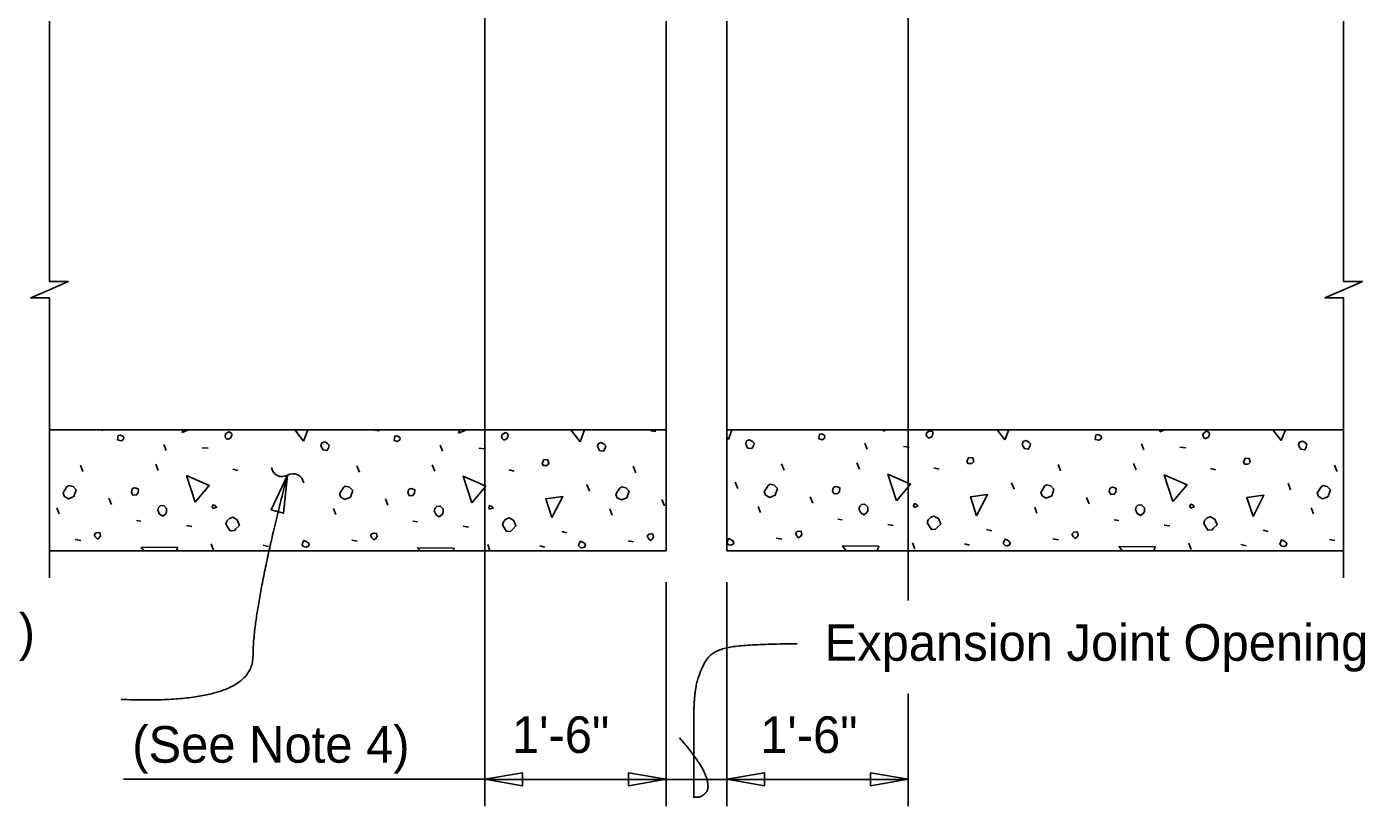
# Model space of a CAD drawing. Extents: x 110698 to 110915, y 110390 to 110472.
# Drawn here: x 110797.65 to 110805.03, y 110451.49 to 110455.78 of the extents above; entities that cross this region are included whole.
import ezdxf

# ---------------------------------------------------------------- set-up
doc = ezdxf.new("R2010")
doc.units = 0
for name, color, linetype in [('AdhocPoint_dp', 7, 'Continuous'), ('Border', 7, 'Continuous'), ('PlotBorder_dp', 7, 'Continuous'), ('SheetBorder_dp', 7, 'Continuous'), ('SheetLines_dp', 7, 'Continuous')]:
    doc.layers.add(name, color=color, linetype=linetype)

msp = doc.modelspace()

# ---------------------------------------------------------------- linework, layer by layer
at = {"layer": 'AdhocPoint_dp'}
for p, q in [((110800.1776, 110464.1815), (110800.1776, 110451.4891)), ((110802.5109, 110464.1815), (110802.5109, 110452.6217)), ((110802.5109, 110452.1086), (110802.5109, 110451.4891))]:
    msp.add_line(p, q, dxfattribs=at)
at = {"layer": 'Border'}
msp.add_line((110800.1776, 110451.6372), (110798.185, 110451.6372), dxfattribs=at)
at = {"layer": 'PlotBorder_dp'}
for p, q in [((110801.1776, 110452.7232), (110801.1776, 110451.4891)), ((110801.5109, 110452.7232), (110801.5109, 110451.4891)), ((110802.5109, 110451.6371), (110800.1776, 110451.6371))]:
    msp.add_line(p, q, dxfattribs=at)
for points in [[(110797.7777, 110455.8133), (110797.7777, 110454.3793), (110797.8811, 110454.3793), (110797.7777, 110454.3343), (110797.6744, 110454.2893), (110797.7777, 110454.2893), (110797.7777, 110452.7468)], [(110804.9108, 110455.8133), (110804.9108, 110454.3793), (110805.0141, 110454.3793), (110804.9108, 110454.3343), (110804.8075, 110454.2893), (110804.9108, 110454.2893), (110804.9108, 110452.7468)]]:
    msp.add_lwpolyline(points, dxfattribs=at)
for points in [[(110799.0893, 110453.3129), (110799.067, 110453.1028), (110798.9991, 110453.1219)], [(110800.1776, 110451.6372), (110800.3858, 110451.6725), (110800.3858, 110451.602)], [(110801.1776, 110451.6372), (110800.9693, 110451.602), (110800.9693, 110451.6725)], [(110801.5109, 110451.6372), (110801.7192, 110451.602), (110801.7192, 110451.6725)], [(110802.5109, 110451.6372), (110802.3027, 110451.6725), (110802.3027, 110451.602)]]:
    msp.add_lwpolyline(points, close=True, dxfattribs=at)
for centre, start, end in [((110799.0602, 110453.364), 188.42943, 300.15665), ((110799.1201, 110453.2609), 8.42943, 120.15665)]:
    msp.add_arc(centre, 0.0596, start, end, dxfattribs=at)
for points in [[(110798.1728, 110452.0773), (110798.8987, 110452.0476), (110798.9003, 110452.5839), (110799.0894, 110453.3127)], [(110801.2506, 110451.8656), (110801.3686, 110451.7293), (110801.4201, 110451.59), (110801.3717, 110451.5386), (110801.3286, 110451.5386), (110801.3286, 110451.5386), (110801.3286, 110451.7899), (110801.3286, 110452.0927), (110801.3596, 110452.229), (110801.4322, 110452.3532), (110801.6653, 110452.3834), (110801.8984, 110452.3834)]]:
    msp.add_open_spline(points, degree=2, dxfattribs=at)
at = {"layer": 'SheetBorder_dp'}
for p, q in [((110798.0532, 110453.5632), (110798.072, 110453.5595)), ((110799.5693, 110453.5613), (110799.5958, 110453.556)), ((110801.0931, 110453.5577), (110801.1196, 110453.5524)), ((110803.4597, 110453.5632), (110803.4608, 110453.563)), ((110798.4202, 110453.4481), (110798.4079, 110453.4817)), ((110798.62, 110453.464), (110798.6518, 110453.4605)), ((110799.9441, 110453.4446), (110799.9317, 110453.4782)), ((110802.2852, 110453.4552), (110802.2728, 110453.4888)), ((110802.4849, 110453.4711), (110802.5168, 110453.4676)), ((110803.809, 110453.4517), (110803.7966, 110453.4852)), ((110804.0088, 110453.4676), (110804.0406, 110453.464)), ((110800.1438, 110453.4605), (110800.1756, 110453.457)), ((110797.9624, 110453.3332), (110797.9482, 110453.3686)), ((110798.3778, 110453.3385), (110798.3637, 110453.3739)), ((110798.7879, 110453.3456), (110798.8162, 110453.3385)), ((110799.4862, 110453.3297), (110799.4721, 110453.365)), ((110799.9016, 110453.335), (110799.8875, 110453.3703)), ((110800.3117, 110453.3421), (110800.34, 110453.335)), ((110801.01, 110453.3261), (110800.9959, 110453.3615)), ((110801.8273, 110453.3403), (110801.8132, 110453.3756)), ((110802.2428, 110453.3456), (110802.2286, 110453.3809)), ((110802.6529, 110453.3527), (110802.6812, 110453.3456)), ((110803.3512, 110453.3368), (110803.337, 110453.3721)), ((110803.7666, 110453.3421), (110803.7524, 110453.3774)), ((110804.1767, 110453.3491), (110804.205, 110453.3421)), ((110804.875, 110453.3332), (110804.8608, 110453.3686)), ((110800.7537, 110453.2254), (110800.7395, 110453.2607)), ((110801.571, 110453.2395), (110801.5569, 110453.2749)), ((110803.0948, 110453.236), (110803.0807, 110453.2713)), ((110804.6186, 110453.2325), (110804.6045, 110453.2678)), ((110798.1197, 110453.1511), (110798.1056, 110453.1865)), ((110799.6435, 110453.1476), (110799.6294, 110453.183)), ((110801.1673, 110453.1441), (110801.1532, 110453.1794)), ((110801.9847, 110453.1582), (110801.9705, 110453.1936)), ((110803.5085, 110453.1547), (110803.4943, 110453.19)), ((110797.8316, 110453.0999), (110797.8192, 110453.1335)), ((110799.3554, 110453.0963), (110799.343, 110453.1299)), ((110800.8792, 110453.0928), (110800.8668, 110453.1264)), ((110801.6965, 110453.1069), (110801.6841, 110453.1405)), ((110803.2203, 110453.1034), (110803.208, 110453.137)), ((110804.7442, 110453.0999), (110804.7318, 110453.1335)), ((110798.2576, 110453.0627), (110798.2823, 110453.0592)), ((110798.5334, 110453.0345), (110798.5634, 110453.0292)), ((110799.7814, 110453.0592), (110799.8062, 110453.0557)), ((110800.0572, 110453.0309), (110800.0872, 110453.0256)), ((110802.1226, 110453.0698), (110802.1473, 110453.0663)), ((110802.3983, 110453.0415), (110802.4284, 110453.0362)), ((110803.6464, 110453.0663), (110803.6711, 110453.0627)), ((110803.9221, 110453.038), (110803.9522, 110453.0327)), ((110797.92, 110452.9584), (110797.95, 110452.9531)), ((110799.4438, 110452.9549), (110799.4738, 110452.9496)), ((110800.6017, 110453.0026), (110800.6299, 110452.9956)), ((110800.9676, 110452.9514), (110800.9976, 110452.9461)), ((110801.7849, 110452.9655), (110801.815, 110452.9602)), ((110802.9428, 110453.0133), (110802.9711, 110453.0062)), ((110803.3087, 110452.962), (110803.3388, 110452.9567)), ((110804.4666, 110453.0097), (110804.4949, 110453.0026)), ((110804.8325, 110452.9584), (110804.8626, 110452.9531)), ((110798.6819, 110452.9001), (110798.6695, 110452.9337)), ((110798.9559, 110452.9266), (110798.9842, 110452.9196)), ((110800.2057, 110452.8966), (110800.1933, 110452.9302)), ((110800.4797, 110452.9231), (110800.508, 110452.916)), ((110802.5468, 110452.9072), (110802.5344, 110452.9408)), ((110802.8208, 110452.9337), (110802.8491, 110452.9266)), ((110804.0706, 110452.9036), (110804.0583, 110452.9372)), ((110804.3446, 110452.9302), (110804.3729, 110452.9231))]:
    msp.add_line(p, q, dxfattribs=at)
for points in [[(110798.5086, 110453.5471), (110798.5136, 110453.5632)], [(110798.5445, 110453.5632), (110798.5086, 110453.5471)], [(110798.7561, 110453.5118), (110798.7632, 110453.5118), (110798.7773, 110453.5188), (110798.7826, 110453.5347), (110798.7809, 110453.5436), (110798.7667, 110453.5507), (110798.749, 110453.54), (110798.7455, 110453.5294), (110798.749, 110453.5188), (110798.7561, 110453.5118)], [(110799.1786, 110453.4994), (110799.1301, 110453.5632)], [(110799.2025, 110453.5632), (110799.1786, 110453.4994)], [(110800.0324, 110453.5436), (110800.0385, 110453.5632)], [(110800.0762, 110453.5632), (110800.0324, 110453.5436)], [(110800.2799, 110453.5082), (110800.287, 110453.5082), (110800.3011, 110453.5153), (110800.3064, 110453.5312), (110800.3047, 110453.54), (110800.2905, 110453.5471), (110800.2729, 110453.5365), (110800.2693, 110453.5259), (110800.2729, 110453.5153), (110800.2799, 110453.5082)], [(110800.7024, 110453.4959), (110800.6512, 110453.5632)], [(110800.7276, 110453.5632), (110800.7024, 110453.4959)], [(110801.5396, 110453.5632), (110801.5197, 110453.51)], [(110802.0183, 110453.5135), (110802.0377, 110453.5082), (110802.0501, 110453.5171), (110802.0518, 110453.5294), (110802.0483, 110453.533), (110802.0342, 110453.54), (110802.0218, 110453.5383), (110802.02, 110453.5259), (110802.0183, 110453.5135)], [(110802.3736, 110453.5542), (110802.3764, 110453.5632)], [(110802.3937, 110453.5632), (110802.3736, 110453.5542)], [(110802.6211, 110453.5188), (110802.6281, 110453.5188), (110802.6423, 110453.5259), (110802.6476, 110453.5418), (110802.6458, 110453.5507), (110802.6317, 110453.5577), (110802.614, 110453.5471), (110802.6105, 110453.5365), (110802.614, 110453.5259), (110802.6211, 110453.5188)], [(110803.0436, 110453.5065), (110803.0004, 110453.5632)], [(110803.0648, 110453.5632), (110803.0436, 110453.5065)], [(110803.5421, 110453.51), (110803.5615, 110453.5047), (110803.5739, 110453.5135), (110803.5757, 110453.5259), (110803.5721, 110453.5294), (110803.558, 110453.5365), (110803.5456, 110453.5347), (110803.5438, 110453.5224), (110803.5421, 110453.51)], [(110803.8974, 110453.5507), (110803.9013, 110453.5632)], [(110803.9254, 110453.5632), (110803.8974, 110453.5507)], [(110804.1449, 110453.5153), (110804.1519, 110453.5153), (110804.1661, 110453.5224), (110804.1714, 110453.5383), (110804.1696, 110453.5471), (110804.1555, 110453.5542), (110804.1378, 110453.5436), (110804.1343, 110453.533), (110804.1378, 110453.5224), (110804.1449, 110453.5153)], [(110804.5674, 110453.5029), (110804.5215, 110453.5632)], [(110804.5899, 110453.5632), (110804.5674, 110453.5029)], [(110798.1533, 110453.5065), (110798.1727, 110453.5012), (110798.1851, 110453.51), (110798.1869, 110453.5224), (110798.1834, 110453.5259), (110798.1692, 110453.533), (110798.1568, 110453.5312), (110798.1551, 110453.5188), (110798.1533, 110453.5065)], [(110799.2776, 110453.4676), (110799.2864, 110453.4517), (110799.3077, 110453.4481), (110799.3165, 110453.464), (110799.32, 110453.4782), (110799.3112, 110453.487), (110799.2953, 110453.4959), (110799.2794, 110453.4905), (110799.2741, 110453.4746), (110799.2776, 110453.4676)], [(110799.6771, 110453.5029), (110799.6966, 110453.4976), (110799.7089, 110453.5065), (110799.7107, 110453.5188), (110799.7072, 110453.5224), (110799.693, 110453.5294), (110799.6807, 110453.5277), (110799.6789, 110453.5153), (110799.6771, 110453.5029)], [(110800.8014, 110453.464), (110800.8103, 110453.4481), (110800.8315, 110453.4446), (110800.8403, 110453.4605), (110800.8438, 110453.4746), (110800.835, 110453.4835), (110800.8191, 110453.4923), (110800.8032, 110453.487), (110800.7979, 110453.4711), (110800.8014, 110453.464)], [(110801.5197, 110453.51), (110801.5109, 110453.5216)], [(110801.6187, 110453.4782), (110801.6276, 110453.4623), (110801.6488, 110453.4587), (110801.6576, 110453.4746), (110801.6612, 110453.4888), (110801.6523, 110453.4976), (110801.6364, 110453.5065), (110801.6205, 110453.5012), (110801.6152, 110453.4852), (110801.6187, 110453.4782)], [(110803.1426, 110453.4746), (110803.1514, 110453.4587), (110803.1726, 110453.4552), (110803.1814, 110453.4711), (110803.185, 110453.4852), (110803.1761, 110453.4941), (110803.1602, 110453.5029), (110803.1443, 110453.4976), (110803.139, 110453.4817), (110803.1426, 110453.4746)], [(110804.6664, 110453.4711), (110804.6752, 110453.4552), (110804.6964, 110453.4517), (110804.7053, 110453.4676), (110804.7088, 110453.4817), (110804.7, 110453.4905), (110804.684, 110453.4994), (110804.6681, 110453.4941), (110804.6628, 110453.4782), (110804.6664, 110453.4711)], [(110800.4991, 110453.3668), (110800.5203, 110453.3668), (110800.5309, 110453.3774), (110800.5256, 110453.3969), (110800.5027, 110453.3986), (110800.4991, 110453.388), (110800.4938, 110453.3792), (110800.4991, 110453.3668), (110800.4956, 110453.3703)], [(110802.8403, 110453.3774), (110802.8615, 110453.3774), (110802.8721, 110453.388), (110802.8668, 110453.4075), (110802.8438, 110453.4092), (110802.8403, 110453.3986), (110802.835, 110453.3898), (110802.8403, 110453.3774), (110802.8367, 110453.3809)], [(110804.3641, 110453.3739), (110804.3853, 110453.3739), (110804.3959, 110453.3845), (110804.3906, 110453.4039), (110804.3676, 110453.4057), (110804.3641, 110453.3951), (110804.3588, 110453.3862), (110804.3641, 110453.3739), (110804.3605, 110453.3774)], [(110802.4461, 110453.1706), (110802.3983, 110453.3173), (110802.5238, 110453.2625), (110802.4461, 110453.1706)], [(110797.8599, 110453.1953), (110797.8828, 110453.183), (110797.9129, 110453.1953), (110797.9253, 110453.2325), (110797.9076, 110453.2501), (110797.8846, 110453.2554), (110797.874, 110453.2484), (110797.8616, 110453.2289), (110797.8528, 110453.213), (110797.8599, 110453.1953)], [(110798.2293, 110453.2183), (110798.2382, 110453.2024), (110798.2576, 110453.2042), (110798.2664, 110453.2165), (110798.2682, 110453.236), (110798.2558, 110453.2413), (110798.247, 110453.2431), (110798.2364, 110453.2395), (110798.2329, 110453.236), (110798.2293, 110453.2183)], [(110798.5811, 110453.1635), (110798.5334, 110453.3102), (110798.6589, 110453.2554), (110798.5811, 110453.1635)], [(110799.3837, 110453.1918), (110799.4066, 110453.1794), (110799.4367, 110453.1918), (110799.4491, 110453.2289), (110799.4314, 110453.2466), (110799.4084, 110453.2519), (110799.3978, 110453.2448), (110799.3854, 110453.2254), (110799.3766, 110453.2095), (110799.3837, 110453.1918)], [(110800.1049, 110453.16), (110800.0572, 110453.3067), (110800.1827, 110453.2519), (110800.1049, 110453.16)], [(110800.9075, 110453.1883), (110800.9305, 110453.1759), (110800.9605, 110453.1883), (110800.9729, 110453.2254), (110800.9552, 110453.2431), (110800.9322, 110453.2484), (110800.9216, 110453.2413), (110800.9093, 110453.2218), (110800.9004, 110453.2059), (110800.9075, 110453.1883)], [(110801.7248, 110453.2024), (110801.7478, 110453.19), (110801.7778, 110453.2024), (110801.7902, 110453.2395), (110801.7725, 110453.2572), (110801.7496, 110453.2625), (110801.7389, 110453.2554), (110801.7266, 110453.236), (110801.7177, 110453.2201), (110801.7248, 110453.2024)], [(110802.0943, 110453.2254), (110802.1031, 110453.2095), (110802.1226, 110453.2112), (110802.1314, 110453.2236), (110802.1332, 110453.2431), (110802.1208, 110453.2484), (110802.1119, 110453.2501), (110802.1013, 110453.2466), (110802.0978, 110453.2431), (110802.0943, 110453.2254)], [(110803.2486, 110453.1989), (110803.2716, 110453.1865), (110803.3017, 110453.1989), (110803.314, 110453.236), (110803.2963, 110453.2537), (110803.2734, 110453.259), (110803.2628, 110453.2519), (110803.2504, 110453.2325), (110803.2415, 110453.2165), (110803.2486, 110453.1989)], [(110803.6181, 110453.2218), (110803.6269, 110453.2059), (110803.6464, 110453.2077), (110803.6552, 110453.2201), (110803.657, 110453.2395), (110803.6446, 110453.2448), (110803.6358, 110453.2466), (110803.6252, 110453.2431), (110803.6216, 110453.2395), (110803.6181, 110453.2218)], [(110803.9699, 110453.167), (110803.9221, 110453.3138), (110804.0477, 110453.259), (110803.9699, 110453.167)], [(110804.7724, 110453.1953), (110804.7954, 110453.183), (110804.8255, 110453.1953), (110804.8378, 110453.2325), (110804.8202, 110453.2501), (110804.7972, 110453.2554), (110804.7866, 110453.2484), (110804.7742, 110453.2289), (110804.7654, 110453.213), (110804.7724, 110453.1953)], [(110799.7531, 110453.2148), (110799.762, 110453.1989), (110799.7814, 110453.2006), (110799.7903, 110453.213), (110799.792, 110453.2325), (110799.7796, 110453.2378), (110799.7708, 110453.2395), (110799.7602, 110453.236), (110799.7567, 110453.2325), (110799.7531, 110453.2148)], [(110800.5469, 110453.0787), (110800.5133, 110453.183), (110800.607, 110453.1953), (110800.5469, 110453.0787)], [(110802.888, 110453.0893), (110802.8544, 110453.1936), (110802.9481, 110453.2059), (110802.888, 110453.0893)], [(110804.4118, 110453.0857), (110804.3782, 110453.19), (110804.4719, 110453.2024), (110804.4118, 110453.0857)], [(110798.3743, 110453.1193), (110798.3849, 110453.0981), (110798.4026, 110453.0875), (110798.4167, 110453.0981), (110798.4238, 110453.1087), (110798.4238, 110453.1299), (110798.4079, 110453.1458), (110798.3884, 110453.1441), (110798.3796, 110453.1352), (110798.3743, 110453.1193)], [(110798.6801, 110453.1282), (110798.6995, 110453.137), (110798.6925, 110453.1441), (110798.6801, 110453.1494), (110798.6748, 110453.137), (110798.6801, 110453.1282)], [(110799.8981, 110453.1158), (110799.9087, 110453.0946), (110799.9264, 110453.084), (110799.9405, 110453.0946), (110799.9476, 110453.1052), (110799.9476, 110453.1264), (110799.9317, 110453.1423), (110799.9122, 110453.1405), (110799.9034, 110453.1317), (110799.8981, 110453.1158)], [(110800.2039, 110453.1246), (110800.2234, 110453.1335), (110800.2163, 110453.1405), (110800.2039, 110453.1458), (110800.1986, 110453.1335), (110800.2039, 110453.1246)], [(110802.2392, 110453.1264), (110802.2498, 110453.1052), (110802.2675, 110453.0946), (110802.2817, 110453.1052), (110802.2887, 110453.1158), (110802.2887, 110453.137), (110802.2728, 110453.1529), (110802.2534, 110453.1511), (110802.2445, 110453.1423), (110802.2392, 110453.1264)], [(110802.545, 110453.1352), (110802.5645, 110453.1441), (110802.5574, 110453.1511), (110802.545, 110453.1564), (110802.5397, 110453.1441), (110802.545, 110453.1352)], [(110803.763, 110453.1229), (110803.7736, 110453.1016), (110803.7913, 110453.091), (110803.8055, 110453.1016), (110803.8125, 110453.1122), (110803.8125, 110453.1335), (110803.7966, 110453.1494), (110803.7772, 110453.1476), (110803.7683, 110453.1388), (110803.763, 110453.1229)], [(110804.0689, 110453.1317), (110804.0883, 110453.1405), (110804.0812, 110453.1476), (110804.0689, 110453.1529), (110804.0636, 110453.1405), (110804.0689, 110453.1317)], [(110798.7508, 110453.0433), (110798.7738, 110453.0062), (110798.7968, 110453.0079), (110798.8056, 110453.0168), (110798.8251, 110453.0362), (110798.8127, 110453.0663), (110798.7879, 110453.0804), (110798.7703, 110453.0734), (110798.7561, 110453.0592), (110798.7508, 110453.0433)], [(110800.2746, 110453.0398), (110800.2976, 110453.0026), (110800.3206, 110453.0044), (110800.3294, 110453.0133), (110800.3489, 110453.0327), (110800.3365, 110453.0627), (110800.3117, 110453.0769), (110800.2941, 110453.0698), (110800.2799, 110453.0557), (110800.2746, 110453.0398)], [(110802.6158, 110453.0504), (110802.6387, 110453.0133), (110802.6617, 110453.015), (110802.6706, 110453.0239), (110802.69, 110453.0433), (110802.6776, 110453.0734), (110802.6529, 110453.0875), (110802.6352, 110453.0804), (110802.6211, 110453.0663), (110802.6158, 110453.0504)], [(110804.1396, 110453.0468), (110804.1626, 110453.0097), (110804.1855, 110453.0115), (110804.1944, 110453.0203), (110804.2138, 110453.0398), (110804.2014, 110453.0698), (110804.1767, 110453.084), (110804.159, 110453.0769), (110804.1449, 110453.0627), (110804.1396, 110453.0468)], [(110798.0313, 110452.9708), (110798.0419, 110452.9602), (110798.0525, 110452.9673), (110798.0596, 110452.9779), (110798.0561, 110452.9956), (110798.0472, 110452.9973), (110798.0349, 110452.9956), (110798.0243, 110452.985), (110798.0313, 110452.9708)], [(110799.1804, 110452.9178), (110799.1927, 110452.916), (110799.2051, 110452.9213), (110799.2087, 110452.9319), (110799.2034, 110452.9408), (110799.1927, 110452.9478), (110799.1804, 110452.9531), (110799.1733, 110452.939), (110799.1698, 110452.9284), (110799.1804, 110452.9178)], [(110799.5551, 110452.9673), (110799.5657, 110452.9567), (110799.5764, 110452.9638), (110799.5834, 110452.9744), (110799.5799, 110452.992), (110799.5711, 110452.9938), (110799.5587, 110452.992), (110799.5481, 110452.9814), (110799.5551, 110452.9673)], [(110800.7042, 110452.9143), (110800.7166, 110452.9125), (110800.7289, 110452.9178), (110800.7325, 110452.9284), (110800.7272, 110452.9372), (110800.7166, 110452.9443), (110800.7042, 110452.9496), (110800.6971, 110452.9355), (110800.6936, 110452.9249), (110800.7042, 110452.9143)], [(110801.079, 110452.9638), (110801.0896, 110452.9531), (110801.1002, 110452.9602), (110801.1072, 110452.9708), (110801.1037, 110452.9885), (110801.0949, 110452.9903), (110801.0825, 110452.9885), (110801.0719, 110452.9779), (110801.079, 110452.9638)], [(110801.5215, 110452.9284), (110801.5339, 110452.9266), (110801.5463, 110452.9319), (110801.5498, 110452.9425), (110801.5445, 110452.9514), (110801.5339, 110452.9584), (110801.5215, 110452.9638), (110801.5144, 110452.9496), (110801.5109, 110452.939), (110801.5215, 110452.9284)], [(110801.8963, 110452.9779), (110801.9069, 110452.9673), (110801.9175, 110452.9744), (110801.9246, 110452.985), (110801.921, 110453.0026), (110801.9122, 110453.0044), (110801.8998, 110453.0026), (110801.8892, 110452.992), (110801.8963, 110452.9779)], [(110803.0453, 110452.9249), (110803.0577, 110452.9231), (110803.0701, 110452.9284), (110803.0736, 110452.939), (110803.0683, 110452.9478), (110803.0577, 110452.9549), (110803.0453, 110452.9602), (110803.0383, 110452.9461), (110803.0347, 110452.9355), (110803.0453, 110452.9249)], [(110803.4201, 110452.9744), (110803.4307, 110452.9638), (110803.4413, 110452.9708), (110803.4484, 110452.9814), (110803.4448, 110452.9991), (110803.436, 110453.0009), (110803.4236, 110452.9991), (110803.413, 110452.9885), (110803.4201, 110452.9744)], [(110804.5691, 110452.9213), (110804.5815, 110452.9196), (110804.5939, 110452.9249), (110804.5974, 110452.9355), (110804.5921, 110452.9443), (110804.5815, 110452.9514), (110804.5691, 110452.9567), (110804.5621, 110452.9425), (110804.5585, 110452.9319), (110804.5691, 110452.9213)], [(110798.2989, 110452.8966), (110798.2841, 110452.916), (110798.4839, 110452.9143), (110798.4773, 110452.8966)], [(110799.82, 110452.8966), (110799.8079, 110452.9125), (110800.0077, 110452.9107), (110800.0024, 110452.8966)], [(110802.1692, 110452.8966), (110802.1491, 110452.9231), (110802.3488, 110452.9213), (110802.3396, 110452.8966)], [(110803.6903, 110452.8966), (110803.6729, 110452.9196), (110803.8726, 110452.9178), (110803.8647, 110452.8966)]]:
    msp.add_lwpolyline(points, dxfattribs=at)
at = {"layer": 'SheetLines_dp'}
for p, q in [((110801.1776, 110455.8133), (110801.1776, 110452.8966)), ((110801.5109, 110455.8133), (110801.5109, 110452.8966)), ((110797.7777, 110453.5632), (110801.1776, 110453.5632)), ((110801.5109, 110453.5632), (110804.9108, 110453.5632)), ((110797.7777, 110452.8966), (110801.1776, 110452.8966)), ((110801.5109, 110452.8966), (110804.9108, 110452.8966))]:
    msp.add_line(p, q, dxfattribs=at)

# ---------------------------------------------------------------- texts
at = {"layer": 'Border'}
for s, p in [('Expansion Joint Opening', (110802.0499, 110452.2901)), ('1\'-6"', (110800.3268, 110451.7824)), ('1\'-6"', (110801.6951, 110451.7824)), ('(See Note 4)', (110798.2341, 110451.7288))]:
    msp.add_text(s, height=0.2016, dxfattribs=at).set_placement(p)
at = {"layer": 'PlotBorder_dp'}
msp.add_text('Bridge Deck (shown)', height=0.2016, dxfattribs=at).set_placement((110795.196, 110452.3491))

doc.saveas('drawing.dxf')
